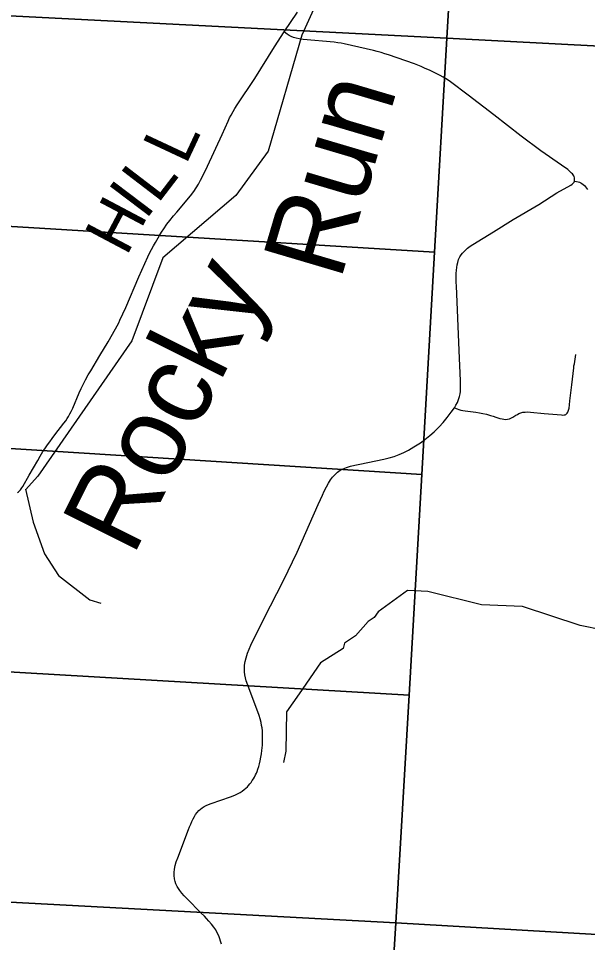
# Model space of a CAD drawing. Extents: x 21.4 to 65.3, y 4 to 26.
# Drawn here: x 26.871 to 27.53, y 19.331 to 20.4 of the extents above; entities that cross this region are included whole.
import ezdxf

# ---------------------------------------------------------------- set-up
doc = ezdxf.new("R2010")
doc.units = 0
for name, color, linetype in [('GM_X_County_Road', 7, 'Continuous'), ('GM_X_County_Road_Text', 7, 'Continuous'), ('GM_X_Minor_River', 7, 'Continuous'), ('GM_X_Minor_River_Text', 7, 'Continuous'), ('GM_X_Section', 7, 'Continuous'), ('GM_X_Township_Road', 7, 'Continuous')]:
    doc.layers.add(name, color=color, linetype=linetype)

msp = doc.modelspace()

# ---------------------------------------------------------------- linework, layer by layer
at = {"layer": 'GM_X_County_Road'}
for points in [[(27.1785, 20.3851), (27.1939, 20.4078)], [(26.8701, 19.852), (26.8713, 19.8528), (26.8723, 19.8537), (26.8733, 19.8549), (26.8742, 19.8561), (26.8752, 19.8574), (26.8762, 19.859), (26.8837, 19.8721), (26.8934, 19.889), (26.8963, 19.8939), (26.8995, 19.8992), (26.9023, 19.9035), (26.9047, 19.907), (26.9073, 19.9106), (26.9101, 19.9145), (26.9134, 19.9188), (26.9238, 19.932), (26.926, 19.935), (26.9276, 19.9374), (26.9292, 19.9399), (26.9307, 19.9429), (26.9322, 19.9458), (26.9339, 19.9495), (26.9415, 19.9672), (26.9437, 19.9721), (26.9463, 19.9775), (26.9488, 19.9823), (26.9519, 19.988), (26.9547, 19.9929), (26.9653, 20.0105), (26.9748, 20.0261), (26.9834, 20.0412), (26.9853, 20.0447), (26.9873, 20.0484), (26.9886, 20.0513), (26.9952, 20.0659), (27.0104, 20.1013), (27.0174, 20.1169), (27.021, 20.1245), (27.0229, 20.1288), (27.0252, 20.1331), (27.0273, 20.1372), (27.0297, 20.1413), (27.0343, 20.1492), (27.0366, 20.153), (27.0392, 20.157), (27.043, 20.1624), (27.0463, 20.1667), (27.0506, 20.1719), (27.0545, 20.1763), (27.0703, 20.1952), (27.074, 20.2001), (27.0769, 20.2045), (27.0794, 20.2089), (27.0819, 20.2133), (27.0848, 20.219), (27.0898, 20.2295), (27.1067, 20.2663), (27.1136, 20.2815), (27.1155, 20.2853), (27.1172, 20.2887), (27.1194, 20.2927), (27.1215, 20.2963), (27.1241, 20.3005), (27.1447, 20.331), (27.1674, 20.3675), (27.1785, 20.3851)], [(27.2459, 19.879), (27.2468, 19.8794), (27.2509, 19.881), (27.2553, 19.8823), (27.2605, 19.8835), (27.2663, 19.8848), (27.2941, 19.8904), (27.3002, 19.892), (27.306, 19.8937), (27.3116, 19.8959), (27.3169, 19.8982), (27.3225, 19.9011), (27.3288, 19.9048), (27.3362, 19.9093), (27.3415, 19.9132), (27.3471, 19.9177), (27.3523, 19.9223), (27.3579, 19.9281), (27.3625, 19.9331), (27.3672, 19.9386), (27.3718, 19.9447), (27.3755, 19.9499), (27.3773, 19.9529), (27.379, 19.9562), (27.3804, 19.9597), (27.3814, 19.9629), (27.3821, 19.966), (27.3825, 19.9689), (27.3827, 19.9723), (27.3828, 19.9758), (27.3826, 19.9813), (27.3812, 20.0163), (27.378, 20.0911), (27.3778, 20.095), (27.3776, 20.0992), (27.3776, 20.1024), (27.3777, 20.1055), (27.3779, 20.1093), (27.3782, 20.1121), (27.3786, 20.1152), (27.3794, 20.1182), (27.3805, 20.1214), (27.3819, 20.1245), (27.3833, 20.1268), (27.385, 20.1289), (27.3867, 20.1307), (27.3884, 20.1324), (27.3907, 20.1346), (27.3937, 20.1368), (27.397, 20.1389), (27.421, 20.1537), (27.4435, 20.1677), (27.4731, 20.1852), (27.4941, 20.1985), (27.5104, 20.2077), (27.512, 20.2087), (27.5131, 20.2098), (27.514, 20.2109), (27.5145, 20.2123), (27.5147, 20.2138), (27.5147, 20.215), (27.5145, 20.2162), (27.5142, 20.2174), (27.5136, 20.2185), (27.5129, 20.2196), (27.5121, 20.2206), (27.5112, 20.2216), (27.5101, 20.2226), (27.5088, 20.2238), (27.5068, 20.2255), (27.4996, 20.2306), (27.4754, 20.2472), (27.4527, 20.2642), (27.4212, 20.289), (27.3915, 20.3117), (27.371, 20.3271), (27.3671, 20.3297), (27.3627, 20.3324), (27.359, 20.3345), (27.3554, 20.3364), (27.3508, 20.3386), (27.3469, 20.3406), (27.3419, 20.3427), (27.337, 20.3448), (27.3293, 20.3478), (27.2994, 20.3582), (27.2951, 20.3597), (27.2908, 20.361), (27.2862, 20.3623), (27.2818, 20.3634), (27.2482, 20.3711), (27.2446, 20.3718), (27.2406, 20.3724), (27.2363, 20.373), (27.2005, 20.3762), (27.196, 20.3768), (27.1926, 20.3775), (27.1893, 20.3785), (27.1868, 20.3796), (27.1845, 20.3808), (27.1821, 20.3824), (27.1785, 20.3851)], [(27.1059, 19.3291), (27.1051, 19.3327), (27.1042, 19.3355), (27.1028, 19.3391), (27.1012, 19.3425), (27.0994, 19.3458), (27.0972, 19.3488), (27.0944, 19.3524), (27.0915, 19.3558), (27.0888, 19.3588), (27.0863, 19.3615), (27.0826, 19.3653), (27.0659, 19.3821), (27.063, 19.3854), (27.0602, 19.3884), (27.058, 19.3912), (27.0562, 19.3938), (27.0548, 19.3962), (27.0534, 19.399), (27.0524, 19.4018), (27.0516, 19.405), (27.0512, 19.4089), (27.0513, 19.4121), (27.0517, 19.4159), (27.0526, 19.4202), (27.0538, 19.4244), (27.0556, 19.4293), (27.0678, 19.4618), (27.0691, 19.465), (27.0704, 19.468), (27.0718, 19.4712), (27.0732, 19.4743), (27.0748, 19.4771), (27.0761, 19.4792), (27.0778, 19.4815), (27.0799, 19.4838), (27.0818, 19.4856), (27.0838, 19.4871), (27.086, 19.4884), (27.0883, 19.4897), (27.0909, 19.4908), (27.0941, 19.4921), (27.1165, 19.4998), (27.1195, 19.5009), (27.1221, 19.5021), (27.1247, 19.5034), (27.1275, 19.5049), (27.13, 19.5065), (27.1322, 19.5082), (27.1342, 19.5098), (27.136, 19.5115), (27.1375, 19.513), (27.1389, 19.5147), (27.1403, 19.5164), (27.1417, 19.5185), (27.1431, 19.5207), (27.1442, 19.5227), (27.1455, 19.5251), (27.1464, 19.5271), (27.1473, 19.5291), (27.1483, 19.5317), (27.1493, 19.5347), (27.1501, 19.5379), (27.1509, 19.5416), (27.1517, 19.5456), (27.1523, 19.5497), (27.1528, 19.5533), (27.1531, 19.5563), (27.1534, 19.5597), (27.1535, 19.5627), (27.1536, 19.5732), (27.1534, 19.5763), (27.153, 19.5796), (27.1525, 19.5823), (27.1518, 19.5856), (27.1507, 19.59), (27.1495, 19.5938), (27.1425, 19.6137), (27.1347, 19.6339), (27.1337, 19.6375), (27.133, 19.6409), (27.1327, 19.6444), (27.1325, 19.6481), (27.1328, 19.652), (27.1334, 19.6563), (27.1345, 19.6608), (27.1362, 19.6659), (27.138, 19.6706), (27.14, 19.6751), (27.1427, 19.681), (27.146, 19.6876), (27.1551, 19.7058), (27.178, 19.75), (27.1937, 19.7828), (27.218, 19.8382), (27.2206, 19.8439), (27.2228, 19.8488), (27.2249, 19.8534), (27.2274, 19.8585), (27.2297, 19.8626), (27.2322, 19.8665), (27.2346, 19.8696), (27.2375, 19.8728), (27.2404, 19.8754), (27.2434, 19.8776), (27.2459, 19.879)]]:
    msp.add_lwpolyline(points, dxfattribs=at)
at = {"layer": 'GM_X_Minor_River'}
for points in [[(27.3815, 20.8819), (27.361, 20.7979), (27.3823, 20.7362), (27.3763, 20.7024), (27.3204, 20.6483), (27.2832, 20.5664), (27.199, 20.3812), (27.1602, 20.2468), (27.1225, 20.1956), (27.0381, 20.1235), (27.0025, 20.0276), (26.8937, 19.871), (26.8794, 19.8549)], [(26.8792, 19.8558), (26.888, 19.8176), (26.9011, 19.781), (26.9176, 19.7558), (26.9539, 19.7278), (26.9664, 19.724)], [(27.5478, 19.6925), (27.5211, 19.6979), (27.4542, 19.7202), (27.407, 19.7221), (27.3447, 19.7374), (27.3213, 19.7385), (27.2873, 19.7137), (27.2829, 19.7071), (27.2756, 19.7027), (27.2611, 19.6861), (27.2484, 19.6774), (27.247, 19.6714), (27.2208, 19.6547), (27.1959, 19.6191), (27.1813, 19.5983), (27.1807, 19.5527), (27.178, 19.5395)]]:
    msp.add_lwpolyline(points, dxfattribs=at)
at = {"layer": 'GM_X_Section'}
for points in [[(26.6312, 20.5264), (27.3731, 20.4834), (27.367, 20.3777), (26.6191, 20.4157)], [(27.3731, 20.4834), (28.0222, 20.4469), (28.0334, 20.4311), (28.0422, 20.4171), (28.0647, 20.3839), (28.073, 20.3722), (28.0829, 20.3589), (28.0906, 20.3484), (28.1023, 20.3397), (27.6101, 20.3651), (27.367, 20.3777)], [(26.3352, 20.4317), (26.6191, 20.4157), (27.367, 20.3777), (27.3527, 20.1302), (26.3235, 20.1926)], [(27.367, 20.3777), (27.6101, 20.3651), (27.5883, 20.0453), (27.5709, 19.7889), (27.5549, 19.5538), (27.5403, 19.3404), (27.3079, 19.3538), (27.3231, 19.6175), (27.3378, 19.8728), (27.3527, 20.1302)], [(27.3527, 20.1302), (27.3378, 19.8728), (26.3057, 19.938), (26.3235, 20.1926)], [(26.3057, 19.938), (27.3378, 19.8728), (27.3231, 19.6175), (26.289, 19.6776)], [(27.3231, 19.6175), (27.3079, 19.3538), (26.2711, 19.4096), (26.289, 19.6776)], [(26.2711, 19.4096), (27.3079, 19.3538), (27.2925, 19.1065), (26.2556, 19.168), (26.2708, 19.4063)], [(27.5403, 19.3404), (28.3017, 19.2998), (28.3345, 19.2762), (28.3347, 19.276), (28.3387, 19.2192), (28.3305, 19.1915), (28.269, 18.2956), (27.3744, 18.3474), (27.2401, 18.3567), (27.2592, 18.6074), (27.2763, 18.86), (27.2925, 19.1065), (27.3079, 19.3538)]]:
    msp.add_lwpolyline(points, close=True, dxfattribs=at)
at = {"layer": 'GM_X_Township_Road'}
for points in [[(27.5145, 20.2123), (27.5168, 20.2119), (27.5189, 20.2114), (27.5203, 20.211), (27.5217, 20.2103), (27.5232, 20.2094), (27.5246, 20.2083), (27.526, 20.207), (27.5273, 20.2056), (27.5285, 20.2041), (27.5297, 20.2024)], [(27.3755, 19.9499), (27.3787, 19.9486), (27.3807, 19.9479), (27.3831, 19.9473), (27.3855, 19.9468), (27.3882, 19.9464), (27.4003, 19.9447), (27.4045, 19.9441), (27.4086, 19.9434), (27.4129, 19.9424), (27.4173, 19.9412), (27.4206, 19.9402), (27.4235, 19.9392), (27.4283, 19.9377), (27.4307, 19.9371), (27.4329, 19.9367), (27.435, 19.9365), (27.4372, 19.9367), (27.4393, 19.9372), (27.441, 19.9379), (27.443, 19.939), (27.4467, 19.9413), (27.4485, 19.9423), (27.4503, 19.9432), (27.4524, 19.9441), (27.4549, 19.9447), (27.4573, 19.945), (27.4601, 19.9451), (27.4636, 19.9449), (27.4796, 19.9434), (27.4996, 19.9417), (27.501, 19.9416), (27.5024, 19.9417), (27.5036, 19.9419), (27.5045, 19.9422), (27.5054, 19.9428), (27.5062, 19.9438), (27.5068, 19.9448), (27.5072, 19.9459), (27.5076, 19.9471), (27.5082, 19.9494), (27.5087, 19.9533), (27.5093, 19.9581), (27.5114, 19.9764), (27.5137, 19.9963), (27.5139, 19.9984), (27.5144, 20.0009), (27.5159, 20.0117)]]:
    msp.add_lwpolyline(points, dxfattribs=at)

# ---------------------------------------------------------------- texts
at = {"layer": 'GM_X_County_Road_Text'}
for s, rotation, p in [('L', 64.9447, (27.0648, 20.2299)), ('L', 52.5751, (27.0321, 20.1849)), ('I', 52.8936, (27.0181, 20.1663)), ('H', 62.0916, (26.996, 20.1242))]:
    msp.add_text(s, height=0.0568, rotation=rotation, dxfattribs=at).set_placement(p)
at = {"layer": 'GM_X_Minor_River_Text'}
for s, rotation, p in [('Run', 73.5135, (27.2435, 20.0956)), ('Rocky', 63.5135, (27.0036, 19.7766))]:
    msp.add_text(s, height=0.0947, rotation=rotation, dxfattribs=at).set_placement(p)

doc.saveas('drawing.dxf')
